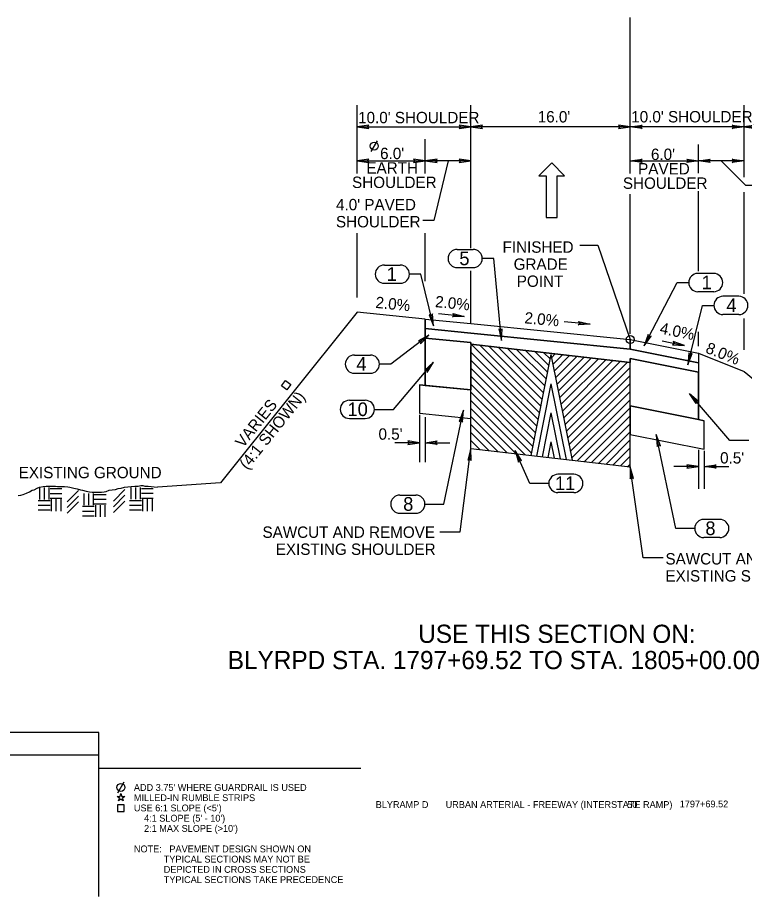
# Model space of a CAD drawing. Extents: x 2003207 to 2014043, y 843846 to 860154.
# Drawn here: x 2013648.6 to 2013712.4, y 844206 to 844283.2 of the extents above; entities that cross this region are included whole.
import ezdxf

# ---------------------------------------------------------------- set-up
doc = ezdxf.new("R2010")
doc.units = 0
for name, color, linetype in [('RD_EX_Pavement_Markings', 7, 'Continuous'), ('RD_EX_Road', 7, 'Continuous'), ('RD_EX_Road_txCode', 7, 'Continuous'), ('RD_QTY_Base_Course', 7, 'Continuous'), ('RD_QTY_ConcPave', 7, 'Continuous'), ('RD_QTY_Intermediate', 7, 'Continuous'), ('RD_QTY_PermVeg', 7, 'Continuous'), ('RD_QTY_Surf_Course', 7, 'Continuous'), ('RD_SHT_Bndy', 7, 'Continuous'), ('RD_SHT_TX', 7, 'Continuous'), ('RD_TX_Misc2', 7, 'Continuous'), ('RD_TX_TypSect', 7, 'Continuous'), ('RD_XS_ExGround', 7, 'Continuous')]:
    doc.layers.add(name, color=color, linetype=linetype)

msp = doc.modelspace()

# ---------------------------------------------------------------- linework, layer by layer
at = {"layer": 'RD_EX_Pavement_Markings'}
msp.add_lwpolyline([(2013695.031, 844265.655), (2013695.991, 844265.655), (2013695.991, 844269.323), (2013696.642, 844269.323), (2013695.511, 844270.455), (2013694.38, 844269.323), (2013695.031, 844269.323)], close=True, dxfattribs=at)
at = {"layer": 'RD_EX_Road'}
for p, q in [((2013688.409, 844254.52), (2013702.409, 844252.91)), ((2013688.409, 844245.353), (2013688.409, 844254.31)), ((2013688.431, 844254.518), (2013694.425, 844248.524)), ((2013689.23, 844254.426), (2013694.543, 844249.113)), ((2013690.029, 844254.334), (2013694.66, 844249.702)), ((2013690.828, 844254.242), (2013694.778, 844250.291)), ((2013688.409, 844253.832), (2013694.307, 844247.934)), ((2013691.627, 844254.15), (2013694.896, 844250.881)), ((2013692.426, 844254.058), (2013695.014, 844251.47)), ((2013693.225, 844253.966), (2013695.132, 844252.059)), ((2013695.441, 844253.607), (2013693.67, 844244.748)), ((2013694.024, 844253.874), (2013695.25, 844252.648)), ((2013694.823, 844253.782), (2013695.368, 844253.238)), ((2013695.441, 844253.607), (2013697.297, 844244.331)), ((2013695.495, 844253.34), (2013695.823, 844253.667)), ((2013695.613, 844252.75), (2013696.457, 844253.595)), ((2013695.731, 844252.161), (2013697.091, 844253.522)), ((2013695.848, 844251.572), (2013697.725, 844253.449)), ((2013688.409, 844253.125), (2013694.189, 844247.345)), ((2013695.966, 844250.983), (2013698.36, 844253.376)), ((2013696.084, 844250.393), (2013698.994, 844253.303)), ((2013696.202, 844249.804), (2013699.628, 844253.23)), ((2013696.32, 844249.215), (2013700.262, 844253.157)), ((2013696.438, 844248.626), (2013700.896, 844253.084)), ((2013696.556, 844248.036), (2013701.53, 844253.011)), ((2013696.673, 844247.447), (2013702.161, 844252.935)), ((2013702.409, 844243.743), (2013702.409, 844252.91)), ((2013688.409, 844252.418), (2013694.071, 844246.756)), ((2013696.791, 844246.858), (2013702.409, 844252.476)), ((2013688.409, 844251.711), (2013693.953, 844246.167)), ((2013696.909, 844246.269), (2013702.409, 844251.769)), ((2013688.409, 844251.003), (2013693.835, 844245.577)), ((2013688.409, 844250.296), (2013693.718, 844244.988)), ((2013695.441, 844251.057), (2013694.168, 844244.691)), ((2013695.441, 844251.057), (2013696.775, 844244.391)), ((2013697.027, 844245.679), (2013702.409, 844251.062)), ((2013697.145, 844245.09), (2013702.409, 844250.355)), ((2013688.409, 844249.589), (2013693.196, 844244.803)), ((2013697.263, 844244.501), (2013702.409, 844249.647)), ((2013688.409, 844248.882), (2013692.66, 844244.631)), ((2013697.748, 844244.279), (2013702.409, 844248.94)), ((2013688.409, 844248.175), (2013691.598, 844244.987)), ((2013695.441, 844248.508), (2013694.667, 844244.634)), ((2013695.441, 844248.508), (2013696.253, 844244.451)), ((2013698.383, 844244.206), (2013702.409, 844248.233)), ((2013688.409, 844247.468), (2013690.799, 844245.079)), ((2013699.017, 844244.134), (2013702.409, 844247.526)), ((2013688.409, 844246.761), (2013690, 844245.17)), ((2013699.651, 844244.061), (2013702.409, 844246.819)), ((2013688.409, 844246.054), (2013689.201, 844245.262)), ((2013695.441, 844245.958), (2013695.165, 844244.576)), ((2013695.441, 844245.958), (2013695.731, 844244.511)), ((2013700.285, 844243.988), (2013702.409, 844246.112)), ((2013688.409, 844245.353), (2013702.409, 844243.743)), ((2013700.919, 844243.915), (2013702.409, 844245.405)), ((2013701.553, 844243.842), (2013702.409, 844244.698)), ((2013702.188, 844243.769), (2013702.409, 844243.991))]:
    msp.add_line(p, q, dxfattribs=at)
at = {"layer": 'RD_EX_Road_txCode'}
msp.add_line((2013657.384, 844215.107), (2013657.95, 844216.05), dxfattribs=at)
for points in [[(2013672.609, 844250.972), (2013672.234, 844250.503), (2013671.765, 844250.878), (2013672.14, 844251.346)], [(2013657.334, 844214.786), (2013657.589, 844214.786), (2013657.667, 844215.028), (2013657.746, 844214.786), (2013658, 844214.786), (2013657.794, 844214.637), (2013657.873, 844214.395), (2013657.667, 844214.544), (2013657.462, 844214.395), (2013657.54, 844214.637)], [(2013657.367, 844213.452), (2013657.967, 844213.452), (2013657.967, 844214.052), (2013657.367, 844214.052)]]:
    msp.add_lwpolyline(points, close=True, dxfattribs=at)
for centre in [(2013702.409, 844254.936), (2013657.667, 844215.578)]:
    msp.add_circle(centre, 0.35, dxfattribs=at)
at = {"layer": 'RD_QTY_Base_Course'}
for p, q in [((2013683.909, 844250.953), (2013688.409, 844250.503)), ((2013683.909, 844250.953), (2013683.909, 844248.453)), ((2013688.409, 844250.503), (2013683.909, 844250.953)), ((2013683.909, 844250.953), (2013683.909, 844250.953)), ((2013683.909, 844250.953), (2013683.909, 844248.453)), ((2013688.409, 844248.003), (2013688.409, 844250.503)), ((2013708.409, 844247.903), (2013702.409, 844249.103)), ((2013683.909, 844248.453), (2013688.409, 844248.003)), ((2013683.909, 844248.453), (2013688.409, 844248.003)), ((2013708.409, 844247.903), (2013708.909, 844247.803)), ((2013708.909, 844247.803), (2013708.409, 844247.903)), ((2013708.909, 844245.303), (2013708.909, 844247.803)), ((2013708.909, 844245.303), (2013708.909, 844247.803)), ((2013702.409, 844246.603), (2013708.909, 844245.303)), ((2013702.409, 844246.603), (2013708.909, 844245.303))]:
    msp.add_line(p, q, dxfattribs=at)
msp.add_lwpolyline([(2013702.409, 844249.103), (2013702.409, 844249.103), (2013702.409, 844246.603)], dxfattribs=at)
at = {"layer": 'RD_QTY_ConcPave'}
for p, q in [((2013684.409, 844256.736), (2013684.409, 844255.903)), ((2013684.409, 844255.07), (2013684.409, 844250.903)), ((2013702.409, 844254.936), (2013708.409, 844253.736)), ((2013708.409, 844253.736), (2013708.409, 844252.07)), ((2013708.409, 844247.903), (2013708.409, 844252.07)), ((2013684.409, 844250.903), (2013688.409, 844250.503)), ((2013702.409, 844249.103), (2013708.409, 844247.903))]:
    msp.add_line(p, q, dxfattribs=at)
for points in [[(2013684.409, 844255.07), (2013688.409, 844254.67), (2013688.409, 844250.503), (2013684.409, 844250.903)], [(2013702.409, 844253.27), (2013708.409, 844252.07), (2013708.409, 844247.903), (2013702.409, 844249.103)]]:
    msp.add_lwpolyline(points, close=True, dxfattribs=at)
at = {"layer": 'RD_QTY_Intermediate'}
for p, q in [((2013684.409, 844255.903), (2013688.409, 844255.503)), ((2013684.409, 844255.903), (2013684.409, 844255.07)), ((2013684.409, 844255.07), (2013688.409, 844254.67)), ((2013688.409, 844255.503), (2013702.409, 844254.103)), ((2013688.409, 844254.52), (2013702.409, 844252.91)), ((2013702.409, 844253.27), (2013708.409, 844252.07)), ((2013708.409, 844252.903), (2013708.409, 844252.07))]:
    msp.add_line(p, q, dxfattribs=at)
msp.add_lwpolyline([(2013684.409, 844255.903), (2013688.409, 844255.503), (2013702.409, 844254.103), (2013708.409, 844252.903), (2013708.409, 844252.07), (2013702.409, 844253.27), (2013702.409, 844252.91), (2013688.409, 844254.52), (2013688.409, 844254.67), (2013684.409, 844255.07)], close=True, dxfattribs=at)
at = {"layer": 'RD_QTY_PermVeg'}
for p, q in [((2013678.409, 844257.336), (2013666.409, 844242.336)), ((2013684.409, 844256.736), (2013678.409, 844257.336)), ((2013708.409, 844253.736), (2013712.409, 844252.136)), ((2013712.409, 844252.136), (2013724.409, 844242.136))]:
    msp.add_line(p, q, dxfattribs=at)
at = {"layer": 'RD_QTY_Surf_Course'}
for p, q in [((2013684.409, 844256.736), (2013688.409, 844256.336)), ((2013688.409, 844256.336), (2013702.409, 844254.936)), ((2013702.409, 844254.936), (2013708.409, 844253.736)), ((2013702.409, 844254.103), (2013708.409, 844252.903))]:
    msp.add_line(p, q, dxfattribs=at)
for points in [[(2013684.409, 844255.903), (2013684.409, 844256.736), (2013688.409, 844256.336), (2013702.409, 844254.936), (2013702.409, 844254.103), (2013688.409, 844255.503)], [(2013702.409, 844254.103), (2013702.409, 844254.936), (2013708.409, 844253.736), (2013708.409, 844252.903)]]:
    msp.add_lwpolyline(points, close=True, dxfattribs=at)
at = {"layer": 'RD_SHT_Bndy'}
for p, q in [((2013655.72, 844220.41), (2013615.72, 844220.41)), ((2013655.72, 844218.41), (2013655.72, 844220.41)), ((2013655.72, 844218.41), (2013615.72, 844218.41)), ((2013655.72, 844205.992), (2013655.72, 844218.41)), ((2013678.754, 844217.242), (2013655.754, 844217.242))]:
    msp.add_line(p, q, dxfattribs=at)
at = {"layer": 'RD_TX_Misc2'}
for p, q in [((2013687.211, 844262.857), (2013688.611, 844262.857)), ((2013680.812, 844261.479), (2013682.212, 844261.479)), ((2013687.211, 844261.257), (2013688.611, 844261.257)), ((2013709.746, 844260.743), (2013708.346, 844260.743)), ((2013680.812, 844259.879), (2013682.212, 844259.879)), ((2013709.746, 844259.143), (2013708.346, 844259.143)), ((2013711.956, 844258.734), (2013710.556, 844258.734)), ((2013711.956, 844257.134), (2013710.556, 844257.134)), ((2013678.181, 844253.572), (2013679.581, 844253.572)), ((2013678.181, 844251.972), (2013679.581, 844251.972)), ((2013677.736, 844249.595), (2013679.136, 844249.595)), ((2013677.736, 844247.995), (2013679.136, 844247.995)), ((2013697.459, 844243.09), (2013696.059, 844243.09)), ((2013682.174, 844241.271), (2013683.574, 844241.271)), ((2013697.459, 844241.49), (2013696.059, 844241.49)), ((2013682.174, 844239.671), (2013683.574, 844239.671)), ((2013710.277, 844239.134), (2013708.877, 844239.134)), ((2013710.277, 844237.534), (2013708.877, 844237.534))]:
    msp.add_line(p, q, dxfattribs=at)
for centre, start, end in [((2013687.211, 844262.057), 90, 270), ((2013688.611, 844262.057), 270, 90), ((2013680.812, 844260.679), 90, 270), ((2013682.212, 844260.679), 270, 90), ((2013708.346, 844259.943), 90, 270), ((2013709.746, 844259.943), 270, 90), ((2013710.556, 844257.934), 90, 270), ((2013711.956, 844257.934), 270, 90), ((2013678.181, 844252.772), 90, 270), ((2013679.581, 844252.772), 270, 90), ((2013677.736, 844248.795), 90, 270), ((2013679.136, 844248.795), 270, 90), ((2013696.059, 844242.29), 90, 270), ((2013697.459, 844242.29), 270, 90), ((2013682.174, 844240.471), 90, 270), ((2013683.574, 844240.471), 270, 90), ((2013708.877, 844238.334), 90, 270), ((2013710.277, 844238.334), 270, 90)]:
    msp.add_arc(centre, 0.8, start, end, dxfattribs=at)
at = {"layer": 'RD_TX_TypSect'}
for p, q in [((2013702.409, 844269.528), (2013702.409, 844283.233)), ((2013678.409, 844269.526), (2013678.409, 844275.54)), ((2013688.409, 844262.971), (2013688.409, 844275.54)), ((2013712.409, 844269.22), (2013712.409, 844275.54)), ((2013678.409, 844273.633), (2013688.409, 844273.633)), ((2013702.409, 844273.633), (2013688.409, 844273.633)), ((2013712.409, 844273.633), (2013702.409, 844273.633)), ((2013712.409, 844273.633), (2013724.409, 844273.633)), ((2013679.64, 844271.466), (2013680.206, 844272.409)), ((2013684.409, 844269.526), (2013684.409, 844272.539)), ((2013708.409, 844269.572), (2013708.409, 844272.086)), ((2013678.409, 844270.633), (2013684.409, 844270.633)), ((2013688.409, 844270.633), (2013684.409, 844270.633)), ((2013702.409, 844270.633), (2013708.409, 844270.633)), ((2013712.409, 844270.633), (2013708.409, 844270.633)), ((2013702.409, 844255.436), (2013702.409, 844267.726)), ((2013708.409, 844260.931), (2013708.409, 844267.965)), ((2013712.409, 844258.951), (2013712.409, 844267.896)), ((2013678.409, 844258.637), (2013678.409, 844264.279)), ((2013684.409, 844260.064), (2013684.409, 844264.279)), ((2013688.409, 844256.336), (2013688.409, 844260.978)), ((2013687.837, 844256.963), (2013685.56, 844257.19)), ((2013698.9, 844256.279), (2013696.621, 844256.487)), ((2013712.409, 844254.022), (2013712.409, 844256.785)), ((2013708.409, 844254.345), (2013708.409, 844255.627)), ((2013705.217, 844254.808), (2013707.168, 844254.418)), ((2013683.909, 844248.308), (2013683.909, 844244.168)), ((2013684.409, 844248.116), (2013684.409, 844244.168)), ((2013683.909, 844245.869), (2013681.742, 844245.869)), ((2013684.409, 844245.869), (2013686.577, 844245.869)), ((2013708.409, 844245.238), (2013708.409, 844241.828)), ((2013708.909, 844245.145), (2013708.909, 844241.828)), ((2013708.409, 844243.774), (2013706.242, 844243.774)), ((2013708.909, 844243.774), (2013711.077, 844243.774))]:
    msp.add_line(p, q, dxfattribs=at)
for points in [[(2013678.409, 844273.633), (2013679.448, 844273.483), (2013679.288, 844273.633), (2013679.448, 844273.783)], [(2013688.409, 844273.633), (2013687.371, 844273.783), (2013687.531, 844273.633), (2013687.371, 844273.483)], [(2013688.409, 844273.633), (2013689.448, 844273.483), (2013689.288, 844273.633), (2013689.448, 844273.783)], [(2013702.409, 844273.633), (2013701.371, 844273.783), (2013701.531, 844273.633), (2013701.371, 844273.483)], [(2013702.409, 844273.633), (2013703.448, 844273.783), (2013703.288, 844273.633), (2013703.448, 844273.483)], [(2013712.409, 844273.633), (2013711.371, 844273.483), (2013711.531, 844273.633), (2013711.371, 844273.783)], [(2013712.409, 844273.633), (2013713.448, 844273.483), (2013713.288, 844273.633), (2013713.448, 844273.783)], [(2013678.409, 844270.633), (2013679.448, 844270.483), (2013679.288, 844270.633), (2013679.448, 844270.783)], [(2013684.409, 844270.633), (2013683.371, 844270.783), (2013683.531, 844270.633), (2013683.371, 844270.483)], [(2013684.409, 844270.633), (2013685.448, 844270.483), (2013685.288, 844270.633), (2013685.448, 844270.783)], [(2013688.409, 844270.633), (2013687.371, 844270.783), (2013687.531, 844270.633), (2013687.371, 844270.483)], [(2013702.409, 844270.633), (2013703.448, 844270.783), (2013703.288, 844270.633), (2013703.448, 844270.483)], [(2013708.409, 844270.633), (2013707.371, 844270.483), (2013707.531, 844270.633), (2013707.371, 844270.783)], [(2013708.409, 844270.633), (2013709.448, 844270.783), (2013709.288, 844270.633), (2013709.448, 844270.483)], [(2013712.409, 844270.633), (2013711.371, 844270.483), (2013711.531, 844270.633), (2013711.371, 844270.783)], [(2013685.132, 844256.138), (2013685.037, 844257.183), (2013684.928, 844256.993), (2013684.745, 844257.114)], [(2013687.837, 844256.963), (2013686.788, 844256.917), (2013686.962, 844257.05), (2013686.818, 844257.215)], [(2013698.9, 844256.279), (2013697.852, 844256.233), (2013698.026, 844256.367), (2013697.881, 844256.532)], [(2013691.104, 844254.843), (2013691.155, 844255.891), (2013691.021, 844255.718), (2013690.856, 844255.863)], [(2013684.728, 844255.319), (2013683.81, 844254.811), (2013684.028, 844254.788), (2013683.99, 844254.572)], [(2013703.637, 844254.376), (2013704.243, 844255.232), (2013704.037, 844255.158), (2013703.976, 844255.369)], [(2013707.168, 844254.418), (2013706.179, 844254.769), (2013706.307, 844254.59), (2013706.12, 844254.475)], [(2013707.472, 844252.723), (2013707.864, 844253.696), (2013707.681, 844253.577), (2013707.573, 844253.768)], [(2013685.14, 844252.94), (2013684.354, 844252.245), (2013684.572, 844252.27), (2013684.583, 844252.051)], [(2013707.628, 844250.196), (2013708.42, 844249.508), (2013708.202, 844249.531), (2013708.194, 844249.312)], [(2013687.751, 844248.722), (2013687.393, 844247.735), (2013687.573, 844247.861), (2013687.687, 844247.674)], [(2013704.701, 844246.585), (2013704.765, 844245.537), (2013704.879, 844245.724), (2013705.058, 844245.598)], [(2013683.909, 844245.869), (2013682.871, 844246.019), (2013683.031, 844245.869), (2013682.871, 844245.719)], [(2013684.409, 844245.869), (2013685.448, 844246.019), (2013685.288, 844245.869), (2013685.448, 844245.719)], [(2013688.409, 844245.353), (2013688.133, 844244.341), (2013688.301, 844244.481), (2013688.431, 844244.304)], [(2013692.296, 844245.182), (2013692.582, 844244.173), (2013692.654, 844244.38), (2013692.856, 844244.295)], [(2013702.409, 844243.743), (2013702.406, 844242.694), (2013702.532, 844242.873), (2013702.703, 844242.736)], [(2013708.409, 844243.774), (2013707.371, 844243.924), (2013707.531, 844243.774), (2013707.371, 844243.624)], [(2013708.909, 844243.774), (2013709.948, 844243.924), (2013709.788, 844243.774), (2013709.948, 844243.624)]]:
    msp.add_lwpolyline(points, close=True, dxfattribs=at)
for points in [[(2013686.409, 844270.633), (2013685.169, 844265.387), (2013684.181, 844265.387)], [(2013714.927, 844268.485), (2013712.567, 844268.485), (2013710.409, 844270.629)], [(2013697.983, 844263.221), (2013699.552, 844263.221), (2013702.409, 844254.936)], [(2013691.104, 844254.843), (2013690.42, 844262.057), (2013689.411, 844262.057)], [(2013685.132, 844256.138), (2013684.021, 844260.679), (2013683.012, 844260.679)], [(2013703.637, 844254.376), (2013706.537, 844259.943), (2013707.546, 844259.943)], [(2013707.472, 844252.723), (2013708.747, 844257.934), (2013709.756, 844257.934)], [(2013684.728, 844255.319), (2013681.39, 844252.772), (2013680.381, 844252.772)], [(2013679.936, 844248.795), (2013681.602, 844248.795), (2013685.14, 844252.94)], [(2013712.832, 844246.05), (2013711.166, 844246.05), (2013707.628, 844250.196)], [(2013684.374, 844240.471), (2013686.04, 844240.471), (2013687.751, 844248.722)], [(2013708.077, 844238.334), (2013706.412, 844238.334), (2013704.701, 844246.585)], [(2013685.693, 844238.038), (2013687.468, 844238.038), (2013688.409, 844245.353)], [(2013695.259, 844242.29), (2013693.594, 844242.29), (2013692.296, 844245.182)], [(2013705.32, 844235.756), (2013703.546, 844235.756), (2013702.409, 844243.743)]]:
    msp.add_lwpolyline(points, dxfattribs=at)
msp.add_circle((2013679.923, 844271.937), 0.35, dxfattribs=at)
at = {"layer": 'RD_XS_ExGround'}
for p, q in [((2013650.509, 844241.93), (2013650.509, 844240.888)), ((2013650.925, 844241.93), (2013650.925, 844240.888)), ((2013651.342, 844241.93), (2013651.342, 844240.888)), ((2013651.439, 844241.833), (2013652.48, 844241.833)), ((2013658.536, 844241.934), (2013658.536, 844240.893)), ((2013658.952, 844241.934), (2013658.952, 844240.893)), ((2013659.369, 844241.934), (2013659.369, 844240.893)), ((2013659.465, 844241.838), (2013660.507, 844241.838)), ((2013666.409, 844242.336), (2013660.879, 844241.95)), ((2013651.439, 844241.416), (2013652.48, 844241.416)), ((2013652.945, 844240.67), (2013653.945, 844241.67)), ((2013652.945, 844240.17), (2013653.945, 844241.17)), ((2013654.399, 844241.416), (2013654.399, 844240.374)), ((2013654.816, 844241.416), (2013654.816, 844240.374)), ((2013655.233, 844241.416), (2013655.233, 844240.374)), ((2013655.329, 844241.319), (2013656.371, 844241.319)), ((2013657.013, 844240.744), (2013658.013, 844241.744)), ((2013657.013, 844240.244), (2013658.013, 844241.244)), ((2013659.465, 844241.421), (2013660.507, 844241.421)), ((2013650.397, 844240.791), (2013651.439, 844240.791)), ((2013650.397, 844240.374), (2013651.439, 844240.374)), ((2013651.439, 844240.999), (2013652.48, 844240.999)), ((2013651.543, 844240.895), (2013651.543, 844239.854)), ((2013651.959, 844240.895), (2013651.959, 844239.854)), ((2013652.376, 844240.895), (2013652.376, 844239.854)), ((2013652.945, 844239.67), (2013653.945, 844240.67)), ((2013654.287, 844240.277), (2013655.329, 844240.277)), ((2013655.329, 844240.902), (2013656.371, 844240.902)), ((2013655.329, 844240.486), (2013656.371, 844240.486)), ((2013655.433, 844240.382), (2013655.433, 844239.34)), ((2013655.85, 844240.382), (2013655.85, 844239.34)), ((2013656.267, 844240.382), (2013656.267, 844239.34)), ((2013657.013, 844239.744), (2013658.013, 844240.744)), ((2013658.424, 844240.796), (2013659.465, 844240.796)), ((2013658.424, 844240.379), (2013659.465, 844240.379)), ((2013659.465, 844241.004), (2013660.507, 844241.004)), ((2013659.57, 844240.9), (2013659.57, 844239.858)), ((2013659.986, 844240.9), (2013659.986, 844239.858)), ((2013660.403, 844240.9), (2013660.403, 844239.858)), ((2013650.397, 844239.958), (2013651.439, 844239.958)), ((2013654.287, 844239.861), (2013655.329, 844239.861)), ((2013658.424, 844239.963), (2013659.465, 844239.963)), ((2013654.287, 844239.444), (2013655.329, 844239.444))]:
    msp.add_line(p, q, dxfattribs=at)
msp.add_lwpolyline([(2013648.653, 844241.217), (2013648.872, 844241.254), (2013649.092, 844241.327), (2013649.385, 844241.437), (2013649.641, 844241.547), (2013649.861, 844241.694), (2013650.044, 844241.73), (2013650.3, 844241.877), (2013650.52, 844241.95), (2013650.849, 844242.023), (2013651.105, 844242.06), (2013651.398, 844242.06), (2013651.728, 844242.06), (2013651.911, 844242.06), (2013652.094, 844242.023), (2013652.313, 844242.023), (2013652.533, 844242.023), (2013652.716, 844242.023), (2013653.009, 844241.987), (2013653.192, 844241.95), (2013653.521, 844241.877), (2013653.814, 844241.803), (2013654.107, 844241.73), (2013654.29, 844241.694), (2013654.619, 844241.62), (2013654.912, 844241.547), (2013655.132, 844241.51), (2013655.315, 844241.51), (2013655.534, 844241.51), (2013655.754, 844241.51), (2013655.974, 844241.51), (2013656.193, 844241.547), (2013656.376, 844241.584), (2013656.633, 844241.694), (2013656.889, 844241.73), (2013657.182, 844241.767), (2013657.438, 844241.84), (2013657.694, 844241.877), (2013657.987, 844241.95), (2013658.28, 844241.987), (2013658.573, 844242.023), (2013658.902, 844242.06), (2013659.195, 844242.06), (2013659.414, 844242.097), (2013659.597, 844242.097), (2013659.781, 844242.06), (2013660.073, 844242.06), (2013660.33, 844242.023), (2013660.586, 844241.987), (2013660.879, 844241.95)], dxfattribs=at)

# ---------------------------------------------------------------- texts
at = {"layer": 'RD_EX_Road_txCode'}
for s, height, p in [('USE THIS SECTION ON:', 1.6, (2013683.787, 844228.274)), ('BLYRPD STA. 1797+69.52 TO STA. 1805+00.00', 1.6, (2013667.057, 844225.968)), ("ADD 3.75' WHERE GUARDRAIL IS USED", 0.6, (2013658.808, 844215.268)), ('MILLED-IN RUMBLE STRIPS', 0.6, (2013658.808, 844214.368)), ("USE 6:1 SLOPE (<5')", 0.6, (2013658.808, 844213.468)), ("    4:1 SLOPE (5' - 10')", 0.6, (2013658.808, 844212.568)), ("    2:1 MAX SLOPE (>10')", 0.6, (2013658.808, 844211.668)), ('NOTE:   PAVEMENT DESIGN SHOWN ON', 0.6, (2013658.808, 844209.868)), (' TYPICAL SECTIONS MAY NOT BE ', 0.6, (2013661.208, 844208.968)), (' DEPICTED IN CROSS SECTIONS', 0.6, (2013661.208, 844208.068)), (' TYPICAL SECTIONS TAKE PRECEDENCE', 0.6, (2013661.208, 844207.168))]:
    msp.add_text(s, height=height, dxfattribs=at).set_placement(p)
at = {"layer": 'RD_SHT_TX'}
for s, p in [('BLYRAMP D', (2013680.049, 844213.768)), ('URBAN ARTERIAL - FREEWAY (INTERSTATE RAMP)', (2013686.194, 844213.768)), ('50', (2013702.145, 844213.768)), ('1797+69.52', (2013706.761, 844213.817))]:
    msp.add_text(s, height=0.6, dxfattribs=at).set_placement(p)
at = {"layer": 'RD_TX_Misc2'}
for s, p in [('5', (2013687.401, 844261.472)), ('1', (2013681.014, 844260.094)), ('1', (2013708.684, 844259.359)), ('4', (2013710.86, 844257.349)), ('4', (2013678.348, 844252.187)), ('10', (2013677.574, 844248.21)), ('11', (2013695.798, 844241.705)), ('8', (2013682.465, 844239.886)), ('8', (2013709.013, 844237.749))]:
    msp.add_text(s, height=1.2, dxfattribs=at).set_placement(p)
at = {"layer": 'RD_TX_TypSect'}
for s, p in [("16.0'", (2013694.284, 844274.014)), ("10.0' SHOULDER", (2013702.501, 844274.019)), ("10.0' SHOULDER", (2013678.505, 844273.945)), ("6.0'", (2013680.438, 844270.791)), ("6.0'", (2013704.232, 844270.715)), ('EARTH', (2013679.233, 844269.523)), ('PAVED', (2013703.106, 844269.447)), ('SHOULDER', (2013677.973, 844268.255)), ('SHOULDER', (2013701.768, 844268.18)), ("4.0' PAVED", (2013676.567, 844266.294)), ('SHOULDER', (2013676.559, 844264.794)), ('FINISHED', (2013691.193, 844262.564)), ('GRADE', (2013692.169, 844261.064)), ('POINT', (2013692.445, 844259.564)), ("0.5'", (2013680.298, 844246.132)), ("0.5'", (2013710.308, 844244.037)), ('EXISTING GROUND', (2013648.687, 844242.747)), ('SAWCUT AND REMOVE', (2013670.106, 844237.507)), ('EXISTING SHOULDER', (2013671.271, 844236.007)), ('SAWCUT AND REMOVE', (2013705.508, 844235.165)), ('EXISTING SHOULDER', (2013705.508, 844233.665))]:
    msp.add_text(s, height=1, dxfattribs=at).set_placement(p)
for s, rotation, p in [('2.0%', 354.28941, (2013679.996, 844257.722)), ('2.0%', 354.28941, (2013685.236, 844257.793)), ('2.0%', 354.7816, (2013693.086, 844256.367)), ('4.0%', 348.69007, (2013704.949, 844255.474)), ('8.0%', 338.19859, (2013708.954, 844253.81)), ('VARIES', 51.34019, (2013668.4, 844245.355)), ('(4:1 SHOWN)', 51.34019, (2013668.779, 844243.428))]:
    msp.add_text(s, height=1, rotation=rotation, dxfattribs=at).set_placement(p)

doc.saveas('drawing.dxf')
